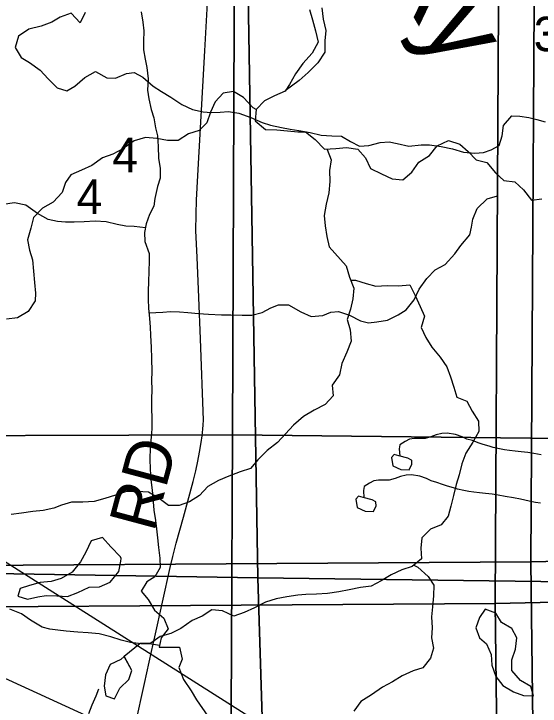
# Model space of a CAD drawing. Extents: x -21.1 to 50.3, y 0 to 22.1.
# Drawn here: x 5.193 to 5.83, y 17.817 to 18.656 of the extents above; entities that cross this region are included whole.
import ezdxf

# ---------------------------------------------------------------- set-up
doc = ezdxf.new("R2010")
doc.units = 0
for name, color, linetype in [('GM_X_County_Road', 7, 'Continuous'), ('GM_X_County_Road_Text', 7, 'Continuous'), ('GM_X_Minor_Lake', 7, 'Continuous'), ('GM_X_Minor_River', 7, 'Continuous'), ('GM_X_Minor_River_Text', 7, 'Continuous'), ('GM_X_Section', 7, 'Continuous'), ('GM_X_Section_Text', 7, 'Continuous'), ('SH_Data', 7, 'Continuous')]:
    doc.layers.add(name, color=color, linetype=linetype)

msp = doc.modelspace()

# ---------------------------------------------------------------- linework, layer by layer
at = {"layer": 'GM_X_County_Road'}
msp.add_lwpolyline([(5.33986, 17.79504), (5.35087, 17.84464), (5.35955, 17.8834), (5.36324, 17.90112), (5.38189, 17.98512), (5.38521, 17.99841), (5.38946, 18.01447), (5.39832, 18.04623), (5.40995, 18.08924), (5.41308, 18.10235), (5.41567, 18.11397), (5.4177, 18.12487), (5.41973, 18.13669), (5.42084, 18.14462), (5.42176, 18.15256), (5.42213, 18.1581), (5.42232, 18.16363), (5.41881, 18.2624), (5.41678, 18.31224), (5.41456, 18.36135), (5.41327, 18.3931), (5.41346, 18.41322), (5.41401, 18.43039), (5.41549, 18.46029), (5.41715, 18.48891), (5.42398, 18.61131), (5.42933, 18.70619)], dxfattribs=at)
at = {"layer": 'GM_X_Minor_Lake'}
for points in [[(5.65909, 18.12032), (5.65338, 18.12216), (5.65039, 18.11833), (5.65202, 18.1081), (5.66155, 18.10403), (5.67179, 18.10338), (5.67475, 18.11024), (5.6747, 18.1148), (5.67432, 18.11517), (5.67012, 18.1174)], [(5.67012, 18.1174), (5.65909, 18.12032)], [(5.6158, 18.0698), (5.61009, 18.07164), (5.6071, 18.06781), (5.60873, 18.05759), (5.61826, 18.05351), (5.6285, 18.05286), (5.63146, 18.05973), (5.63141, 18.06428), (5.63103, 18.06465), (5.62683, 18.06689)], [(5.62683, 18.06689), (5.6158, 18.0698)], [(5.32198, 17.99794), (5.31016, 18.0101), (5.29987, 18.02149), (5.28618, 18.01729), (5.27973, 18.0036), (5.27328, 17.9918), (5.26341, 17.97924), (5.2501, 17.97161), (5.23793, 17.96817), (5.22461, 17.96702), (5.21168, 17.9632), (5.20027, 17.95976), (5.19724, 17.95025), (5.20904, 17.94684), (5.2216, 17.94952)], [(5.32198, 17.99795), (5.31016, 18.0101), (5.29987, 18.02149), (5.28618, 18.01729), (5.27973, 18.0036), (5.27328, 17.9918), (5.26341, 17.97924), (5.2501, 17.97161), (5.23793, 17.96817), (5.22461, 17.96702), (5.21168, 17.9632), (5.20027, 17.95976), (5.19724, 17.95025), (5.20904, 17.94684), (5.2216, 17.94952)], [(5.2216, 17.94952), (5.23187, 17.95106), (5.24481, 17.95069), (5.25774, 17.94995), (5.27029, 17.95491), (5.28398, 17.96139), (5.29654, 17.96179), (5.30909, 17.96713), (5.31972, 17.98007), (5.32236, 17.99262), (5.32244, 17.9961), (5.32198, 17.99794)], [(5.2216, 17.94952), (5.23187, 17.95106), (5.24481, 17.95069), (5.25774, 17.94995), (5.27029, 17.95491), (5.28398, 17.96139), (5.29654, 17.96179), (5.30909, 17.96713), (5.31972, 17.98007), (5.32236, 17.99262), (5.32244, 17.9961), (5.32203, 17.99777)], [(5.81888, 17.84093), (5.80657, 17.84799), (5.7959, 17.86014), (5.79588, 17.87307), (5.80042, 17.886), (5.80193, 17.8997), (5.7962, 17.9111), (5.78364, 17.91831), (5.77677, 17.9297), (5.76383, 17.93463), (5.75699, 17.92435), (5.75245, 17.9118), (5.75703, 17.89964)], [(5.81914, 17.84078), (5.80657, 17.84799), (5.7959, 17.86014), (5.79588, 17.87307), (5.80042, 17.886), (5.80193, 17.8997), (5.7962, 17.9111), (5.78364, 17.91831), (5.77677, 17.9297), (5.76383, 17.93463), (5.75699, 17.92435), (5.75245, 17.9118), (5.75703, 17.89964)], [(5.75703, 17.89964), (5.76541, 17.89242), (5.77114, 17.8795), (5.77192, 17.86657), (5.7765, 17.85289), (5.78527, 17.84187), (5.79822, 17.83428), (5.81002, 17.82974), (5.8222, 17.82937), (5.81888, 17.84093)], [(5.75703, 17.89964), (5.76541, 17.89242), (5.77114, 17.8795), (5.77192, 17.86657), (5.7765, 17.85289), (5.78527, 17.84187), (5.79822, 17.83428), (5.81002, 17.82974), (5.8222, 17.82937), (5.81891, 17.84083)], [(5.32625, 17.8773), (5.32216, 17.8736), (5.30923, 17.8675), (5.30354, 17.85494), (5.30204, 17.84125), (5.30396, 17.82946)], [(5.32615, 17.87721), (5.32216, 17.8736), (5.30923, 17.8675), (5.30354, 17.85494), (5.30204, 17.84125), (5.30396, 17.82946)], [(5.30396, 17.82946), (5.31462, 17.82606), (5.32107, 17.83899), (5.33209, 17.84927), (5.3355, 17.86031), (5.32615, 17.87749)], [(5.30396, 17.82946), (5.31462, 17.82606), (5.32107, 17.83899), (5.33209, 17.84927), (5.3355, 17.86031), (5.32625, 17.8773)]]:
    msp.add_lwpolyline(points, dxfattribs=at)
at = {"layer": 'GM_X_Minor_River'}
for points in [[(5.56566, 18.66338), (5.56759, 18.64969), (5.57065, 18.636), (5.56953, 18.62345), (5.56955, 18.60976), (5.56082, 18.59682), (5.54904, 18.58501), (5.5384, 18.57511), (5.52131, 18.56271)], [(5.55083, 18.66146), (5.55465, 18.64891), (5.5581, 18.6356), (5.56154, 18.62192), (5.55395, 18.6086), (5.54293, 18.59603), (5.53382, 18.58347), (5.52661, 18.57053)], [(5.2789, 18.6579), (5.27308, 18.64505), (5.26219, 18.65693), (5.24885, 18.65213), (5.23854, 18.64615), (5.22559, 18.64135), (5.21074, 18.6377), (5.19813, 18.62909), (5.19419, 18.61546), (5.20128, 18.60323), (5.21146, 18.59705), (5.22466, 18.5878), (5.23404, 18.57745), (5.24493, 18.56632), (5.25666, 18.56278), (5.26659, 18.56838), (5.27847, 18.5789), (5.29145, 18.58636), (5.30542, 18.57862), (5.31566, 18.57814), (5.329, 18.5837), (5.33851, 18.58512), (5.3487, 18.57932), (5.36149, 18.56856), (5.37168, 18.562), (5.38299, 18.55504), (5.39619, 18.54618), (5.40903, 18.54035), (5.42191, 18.53718), (5.43177, 18.53632), (5.4424, 18.53697), (5.45266, 18.53763), (5.46517, 18.5356), (5.47992, 18.53051), (5.49352, 18.5243), (5.50374, 18.52115), (5.51699, 18.51836), (5.5276, 18.51635), (5.53784, 18.51473), (5.55148, 18.51231), (5.56511, 18.50914), (5.57801, 18.50825), (5.58977, 18.50775), (5.60071, 18.50118), (5.61128, 18.49575), (5.62268, 18.4964), (5.63638, 18.50006), (5.6474, 18.50108), (5.65725, 18.49908), (5.67126, 18.49552), (5.68608, 18.49727), (5.69633, 18.49717), (5.71036, 18.49551)], [(5.34705, 18.65846), (5.34894, 18.64594), (5.35007, 18.63533), (5.34968, 18.62243), (5.34968, 18.61257), (5.35157, 18.60119), (5.35384, 18.59095), (5.35535, 18.5773), (5.35458, 18.56364), (5.35609, 18.55302), (5.35912, 18.54013), (5.36215, 18.52989), (5.36441, 18.51775), (5.36668, 18.50827), (5.36744, 18.49538), (5.36781, 18.48134), (5.3697, 18.46845), (5.36969, 18.45707), (5.36665, 18.44683), (5.36361, 18.43242), (5.36209, 18.42294), (5.35678, 18.41307), (5.35298, 18.4017), (5.35108, 18.39108), (5.35145, 18.38008), (5.35675, 18.36566), (5.35637, 18.3558), (5.35598, 18.34443), (5.3556, 18.33077), (5.35521, 18.32091), (5.35521, 18.30991), (5.35558, 18.29929), (5.35709, 18.28678)], [(5.52661, 18.57053), (5.52129, 18.56254), (5.50836, 18.55682), (5.4962, 18.55072), (5.48632, 18.54006), (5.4852, 18.52637), (5.49739, 18.51611), (5.51109, 18.51537), (5.52403, 18.51425), (5.53658, 18.51312), (5.5461, 18.51314), (5.55753, 18.50364), (5.56896, 18.49225), (5.58265, 18.49303), (5.59559, 18.49418), (5.60929, 18.49192), (5.61882, 18.48167), (5.62492, 18.46874), (5.63825, 18.46229), (5.65082, 18.45623), (5.66375, 18.45472), (5.67478, 18.46425), (5.68313, 18.47642), (5.69606, 18.48443), (5.70555, 18.49623), (5.71924, 18.50271), (5.73294, 18.49817), (5.74323, 18.48943), (5.75276, 18.47918), (5.7657, 18.47577), (5.77637, 18.46323), (5.78628, 18.45412), (5.7996, 18.45262), (5.81026, 18.44274), (5.81979, 18.43021), (5.83235, 18.43174)], [(5.48631, 18.54007), (5.48251, 18.54234), (5.4707, 18.55487), (5.45889, 18.56208), (5.44634, 18.55978), (5.43646, 18.5495), (5.43077, 18.53694), (5.4266, 18.52401), (5.41711, 18.51487), (5.40417, 18.51067), (5.39163, 18.50267), (5.37869, 18.50265), (5.36575, 18.50492), (5.35205, 18.50604), (5.33836, 18.50222), (5.32468, 18.49232), (5.31251, 18.48621), (5.29996, 18.48164), (5.28704, 18.47211), (5.27449, 18.46677), (5.26156, 18.46105), (5.25511, 18.45153), (5.25132, 18.43936), (5.2403, 18.42794), (5.22738, 18.4207), (5.21636, 18.40927), (5.21333, 18.39634), (5.20917, 18.38226), (5.21147, 18.36972), (5.21529, 18.35793), (5.21645, 18.34424), (5.21761, 18.33055), (5.21877, 18.31763), (5.21841, 18.30812), (5.21006, 18.29518), (5.19713, 18.28756), (5.18382, 18.28602)], [(5.71036, 18.49551), (5.72399, 18.49233), (5.73762, 18.4884), (5.75127, 18.48712), (5.76153, 18.48815), (5.77105, 18.49109), (5.78059, 18.49632), (5.78451, 18.50805), (5.78578, 18.52057), (5.79615, 18.53262), (5.80564, 18.53215), (5.81663, 18.53052), (5.82647, 18.52814), (5.83631, 18.52538)], [(5.57237, 18.49244), (5.57238, 18.49187), (5.57697, 18.47895), (5.57508, 18.4664), (5.57548, 18.45271), (5.57436, 18.43902), (5.57096, 18.42532), (5.56869, 18.41163), (5.56985, 18.39908), (5.57178, 18.38615), (5.57484, 18.37361), (5.59542, 18.35082), (5.59924, 18.33713), (5.60459, 18.32345), (5.60347, 18.31052), (5.60044, 18.29834), (5.59665, 18.28579), (5.6001, 18.27324), (5.60126, 18.25956), (5.59595, 18.24586), (5.58988, 18.23216), (5.58724, 18.21847), (5.57851, 18.20591), (5.57967, 18.19298), (5.56979, 18.1827), (5.55648, 18.17584), (5.54356, 18.16821), (5.53139, 18.15755), (5.5219, 18.14689), (5.51202, 18.13661), (5.49948, 18.12671), (5.48808, 18.11566), (5.47934, 18.10501), (5.46679, 18.10119), (5.4531, 18.09585), (5.44056, 18.0905), (5.42763, 18.08326), (5.41737, 18.07222), (5.40559, 18.0646), (5.39304, 18.0604), (5.3801, 18.06039), (5.36867, 18.06874), (5.35572, 18.07632), (5.34203, 18.07707), (5.32909, 18.07705), (5.31578, 18.07285), (5.30285, 18.06865), (5.28992, 18.06521), (5.27622, 18.06443), (5.26252, 18.06404), (5.25035, 18.0606), (5.24084, 18.05678), (5.22791, 18.0541), (5.21574, 18.05295), (5.20166, 18.05103), (5.18949, 18.04949)], [(5.35626, 18.29365), (5.37301, 18.29437), (5.38249, 18.2955), (5.39311, 18.29512), (5.40334, 18.29399), (5.41623, 18.29285), (5.42836, 18.29209), (5.44429, 18.29134), (5.45566, 18.29134), (5.46931, 18.29096), (5.48106, 18.29096), (5.49357, 18.29399), (5.50381, 18.29968), (5.51329, 18.30348), (5.52543, 18.30348), (5.54021, 18.29476), (5.55271, 18.28945), (5.56712, 18.29059), (5.5766, 18.29438), (5.58608, 18.29552), (5.59935, 18.29097), (5.61261, 18.28414), (5.62247, 18.28149), (5.63232, 18.28263), (5.64522, 18.2849), (5.65811, 18.29135), (5.66797, 18.29742), (5.67783, 18.30956), (5.6839, 18.32245), (5.69301, 18.33535), (5.70325, 18.34597), (5.71539, 18.35242), (5.72676, 18.36532), (5.73435, 18.37518), (5.74497, 18.38808), (5.74725, 18.39756), (5.74877, 18.40742), (5.75409, 18.42031), (5.76623, 18.43169), (5.77874, 18.43549)], [(5.35207, 18.39664), (5.33819, 18.39828), (5.32833, 18.39866), (5.31772, 18.40094), (5.30445, 18.40397), (5.29118, 18.40472), (5.27792, 18.40397), (5.26578, 18.40358), (5.25517, 18.40358), (5.24531, 18.40434), (5.23432, 18.407), (5.22106, 18.4142), (5.20703, 18.42406), (5.19339, 18.42709), (5.17974, 18.4252)], [(5.60068, 18.33346), (5.60648, 18.33334), (5.61942, 18.32917), (5.63122, 18.32614), (5.64492, 18.32692), (5.65861, 18.32656), (5.67231, 18.32772), (5.6788, 18.3148), (5.68491, 18.3015), (5.69025, 18.28971), (5.68608, 18.27602), (5.69181, 18.26385), (5.69906, 18.25208), (5.70935, 18.23992), (5.71735, 18.22814), (5.72156, 18.21598), (5.72576, 18.20382), (5.72958, 18.19165), (5.74139, 18.18672), (5.74787, 18.17456), (5.7555, 18.1624), (5.7559, 18.14986), (5.74869, 18.13692), (5.74034, 18.1236), (5.73541, 18.11066), (5.73201, 18.09735), (5.7286, 18.08555), (5.72519, 18.07224), (5.72217, 18.05931), (5.71876, 18.04713), (5.71041, 18.03685), (5.69748, 18.03152), (5.68684, 18.02085), (5.68572, 18.0083), (5.6865, 17.99537), (5.67509, 17.98623), (5.66254, 17.98203), (5.65, 17.97631), (5.63783, 17.96907), (5.62567, 17.96259), (5.61273, 17.96067), (5.59904, 17.958), (5.58648, 17.9557), (5.57279, 17.9534), (5.55947, 17.95262), (5.54654, 17.95222), (5.53665, 17.95145), (5.52333, 17.94953), (5.5104, 17.94723), (5.49747, 17.94303), (5.48416, 17.93617), (5.47161, 17.93045), (5.45906, 17.92625), (5.44535, 17.9327), (5.43241, 17.93382), (5.42063, 17.9262), (5.40846, 17.92086), (5.39478, 17.91096), (5.38299, 17.90524), (5.37006, 17.90142), (5.35866, 17.89342), (5.34572, 17.89302), (5.32615, 17.87735)], [(5.35709, 18.28678), (5.35784, 18.27654), (5.35822, 18.26668), (5.35897, 18.25189), (5.35934, 18.23861), (5.35971, 18.2223), (5.35932, 18.21206), (5.3597, 18.2003), (5.35931, 18.18931), (5.35931, 18.17755), (5.35968, 18.16655), (5.35967, 18.15328), (5.35891, 18.14341), (5.35776, 18.13014), (5.35738, 18.11649), (5.35775, 18.10435), (5.3585, 18.09145), (5.36001, 18.07894), (5.36152, 18.06453), (5.36227, 18.05467), (5.36416, 18.04215), (5.36529, 18.03191), (5.3668, 18.02091), (5.36793, 18.00915), (5.36944, 17.99626), (5.36982, 17.98488), (5.36337, 17.97388), (5.35389, 17.96781), (5.34668, 17.95644), (5.35539, 17.94619), (5.36297, 17.9333), (5.37433, 17.92382), (5.37964, 17.91092), (5.37129, 17.89992), (5.36863, 17.88855), (5.38114, 17.88855), (5.39327, 17.88855), (5.39668, 17.87414), (5.3925, 17.8639), (5.39818, 17.84948), (5.40727, 17.83545), (5.41409, 17.82483), (5.44137, 17.78501)], [(5.83141, 18.12177), (5.82264, 18.12324), (5.8154, 18.12434), (5.8074, 18.12544), (5.80017, 18.12616), (5.79331, 18.12688), (5.78722, 18.12761), (5.78112, 18.12871), (5.7735, 18.13057), (5.76854, 18.13206), (5.7613, 18.1343), (5.7552, 18.13617), (5.74833, 18.13879), (5.74147, 18.14065), (5.73575, 18.14328), (5.72773, 18.14627), (5.71783, 18.14774), (5.71136, 18.14732), (5.70452, 18.14576), (5.69806, 18.14345), (5.69084, 18.14151), (5.6779, 18.14144), (5.67219, 18.14065), (5.66688, 18.13796), (5.66043, 18.13374), (5.6597, 18.1288), (5.66015, 18.12004)], [(5.8308, 18.06313), (5.8247, 18.06386), (5.81708, 18.06534), (5.80641, 18.06794), (5.79802, 18.06941), (5.78812, 18.07126), (5.77935, 18.07273), (5.77212, 18.07383), (5.76412, 18.07492), (5.75688, 18.07564), (5.75002, 18.07636), (5.74393, 18.07709), (5.73783, 18.0782), (5.73021, 18.08005), (5.72525, 18.08155), (5.71801, 18.08379), (5.71191, 18.08565), (5.70504, 18.08827), (5.69818, 18.09013), (5.69246, 18.09276), (5.68445, 18.09576), (5.67454, 18.09722), (5.66807, 18.09681), (5.66123, 18.09525), (5.65477, 18.09293), (5.64755, 18.09099), (5.63461, 18.09092), (5.6289, 18.09013), (5.62359, 18.08744), (5.61714, 18.08323), (5.61641, 18.07829), (5.61686, 18.06952)], [(5.67732, 17.98802), (5.68232, 17.98548), (5.69452, 17.97409), (5.70138, 17.96345), (5.70102, 17.95052), (5.6999, 17.93721), (5.69877, 17.92542), (5.69956, 17.91211), (5.69881, 17.89994), (5.70111, 17.8874), (5.69733, 17.87522), (5.68821, 17.86342), (5.67642, 17.85999), (5.66311, 17.85389), (5.65133, 17.84664), (5.63916, 17.84017), (5.62586, 17.83064), (5.61293, 17.82264), (5.60458, 17.81084)], [(5.3691, 17.89055), (5.35688, 17.89234), (5.34702, 17.89272), (5.33375, 17.89423), (5.32276, 17.89689), (5.31025, 17.90106), (5.29585, 17.90447), (5.28258, 17.90599), (5.27007, 17.90674), (5.25604, 17.90788), (5.24581, 17.90902), (5.23633, 17.91015), (5.22685, 17.91281), (5.21283, 17.92115), (5.20184, 17.92874), (5.18782, 17.93443)], [(5.28352, 17.80801), (5.28765, 17.81867), (5.29215, 17.82971), (5.29553, 17.83809)]]:
    msp.add_lwpolyline(points, dxfattribs=at)
at = {"layer": 'GM_X_Section'}
for points in [[(4.46024, 19.14326), (5.46172, 19.1492), (5.45742, 18.14589), (4.45293, 18.14262)], [(5.46172, 19.1492), (6.46467, 19.14528), (6.46827, 18.13471), (5.45742, 18.14589)], [(4.83075, 19.0046), (4.855, 19.00483), (5.82494, 19.00715), (5.81893, 17.99203), (4.83425, 17.98542)], [(6.83581, 19.01172), (6.83569, 18.01448), (5.81893, 17.99203), (5.82494, 19.00715), (5.8818, 19.00728)], [(5.47114, 18.99721), (5.48815, 17.97251), (4.50247, 17.98887), (4.50596, 18.94006), (4.50668, 19.00183)], [(6.50457, 18.98884), (6.51666, 17.95921), (5.48815, 17.97251), (5.47114, 18.99721)], [(4.78746, 18.95409), (4.81171, 18.95431), (5.78166, 18.95663), (5.77564, 17.94152), (4.79096, 17.9349)], [(6.79252, 18.9612), (6.7924, 17.96396), (5.77564, 17.94152), (5.78166, 18.95663), (5.83851, 18.95676)], [(4.45293, 18.14262), (5.45742, 18.14589), (5.45266, 17.13084), (4.44556, 17.13365)], [(5.45742, 18.14589), (6.46827, 18.13471), (6.47301, 17.12604), (6.41542, 17.12601), (5.45266, 17.13084)], [(5.81893, 17.99203), (6.83569, 18.01448), (6.84408, 16.99761), (5.83147, 16.97938)], [(5.81893, 17.99203), (5.83147, 16.97938), (4.84683, 16.96859), (4.83425, 17.98542)], [(4.50247, 17.98887), (5.48815, 17.97251), (5.52017, 16.94387), (4.49435, 16.93023), (4.50289, 17.92975)], [(5.48815, 17.97251), (6.51666, 17.95921), (6.54146, 16.94121), (5.52017, 16.94387)], [(5.77564, 17.94152), (6.7924, 17.96396), (6.8008, 16.94709), (5.78818, 16.92886)], [(5.77564, 17.94152), (5.78818, 16.92886), (4.80354, 16.91807), (4.79096, 17.9349)]]:
    msp.add_lwpolyline(points, close=True, dxfattribs=at)
at = {"layer": 'SH_Data'}
msp.add_lwpolyline([(4.78867, 18.03124), (5.98542, 17.4819), (4.78867, 18.24124)], close=True, dxfattribs=at)

# ---------------------------------------------------------------- texts
at = {"layer": 'GM_X_County_Road_Text'}
msp.add_text('RD', height=0.056818, rotation=75.00543, dxfattribs=at).set_placement((5.36239, 18.02675))
at = {"layer": 'GM_X_Minor_River_Text'}
msp.add_text('Rocky', height=0.094744, rotation=299.98055, dxfattribs=at).set_placement((5.53918, 18.89086))
at = {"layer": 'GM_X_Section_Text'}
for s, height, p in [('30', 0.041856, (5.82253, 18.61081)), ('4', 0.04186, (5.31193, 18.46411)), ('4', 0.04186, (5.26864, 18.41359))]:
    msp.add_text(s, height=height, rotation=0.00001, dxfattribs=at).set_placement(p)

doc.saveas('drawing.dxf')
